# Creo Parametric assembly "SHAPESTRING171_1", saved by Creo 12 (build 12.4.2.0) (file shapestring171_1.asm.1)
Units: Custom; MM, KILOGRAM, SECS

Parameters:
  PTC_WM_ITERATION = "0"
  PTC_WM_VERSION = "-.0"
  PTC_WM_LIFECYCLE_STATE = "In Work"
  PTC_WM_LIFECYCLE = "MO_CADDocument"
  PTC_WM_CREATED_BY = "Maximilian Roepper (Z0017RMS: MO)"
  PTC_WM_CREATED_ON = "18-Sep-26 11:36:42 AM"
  PTC_WM_MODIFIED_BY = "Maximilian Roepper (Z0017RMS: MO)"
  PTC_WM_MODIFIED_ON = "18-Sep-26 11:36:46 AM"
  PDMLINKNUMBER = "PDM000071455162"
  PTC_WM_NUMBER = "PDM000071455162"

Other parameters: WEIGHT, WEIGHT_FACTOR, WEIGHT_ADD, MC_ERRORS, SUPPLIER

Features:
  1. coordinate system
  2. imported feature
  3. component "SHAPESTRING081_1"
  4. component "SHAPESTRING169_1"
  5. component "SHAPESTRING170_1"

Other named items: DRW_VIEW_ORG, ROUGH-GROB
